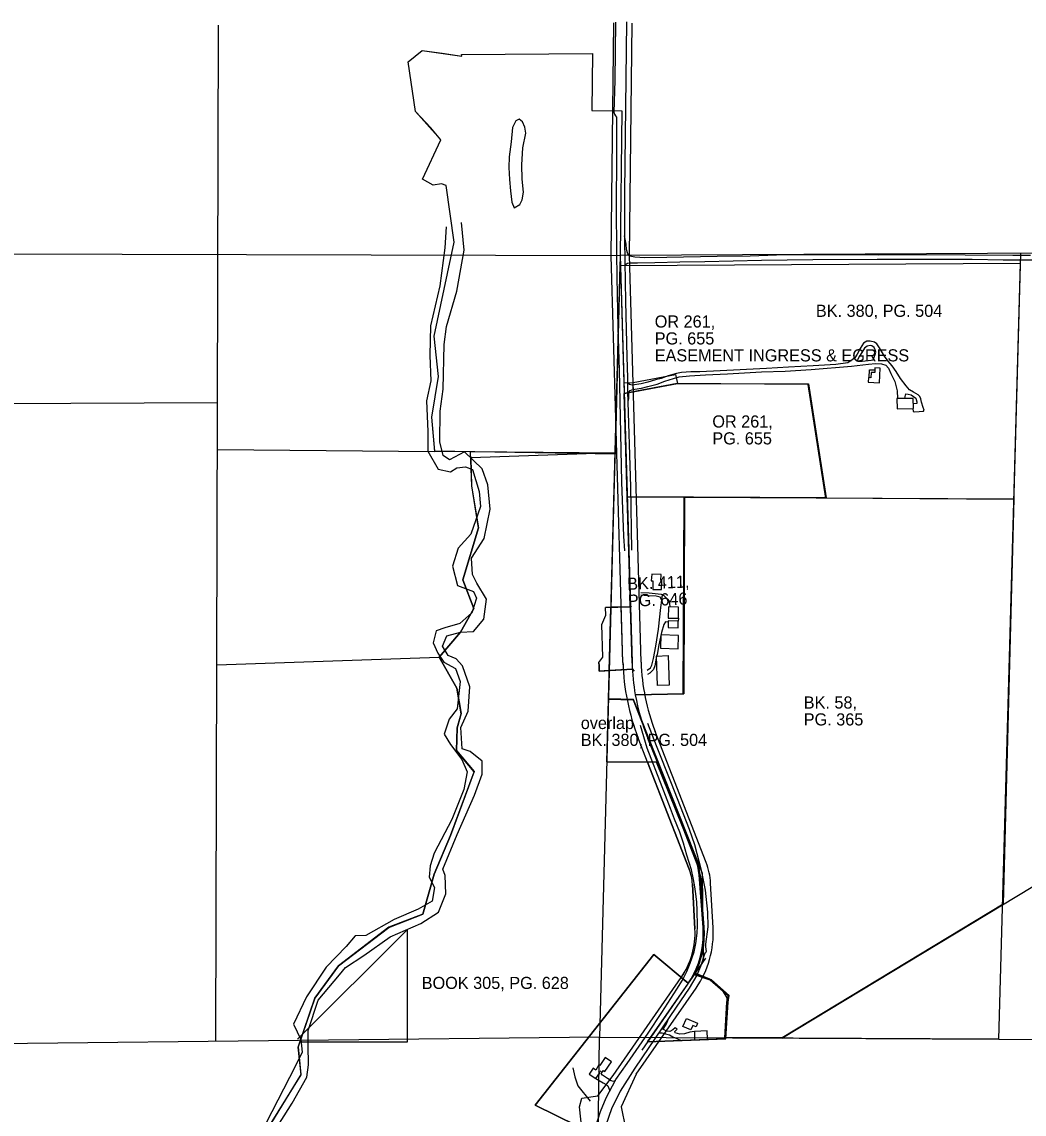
# Model space of a CAD drawing. Extents: x 171944 to 348094, y 278777 to 304794.
# Drawn here: x 175290 to 178592, y 288639 to 292239 of the extents above; entities that cross this region are included whole.
import ezdxf

# ---------------------------------------------------------------- set-up
doc = ezdxf.new("R2010")
doc.units = 0
for name, color, linetype in [('_CIVIL_CONSTRUCTION', 7, 'Continuous'), ('Default', 7, 'Continuous'), ('DR_Ditch', 7, 'Continuous'), ('DR_Pond', 7, 'Continuous'), ('DR_X_Ditch', 7, 'Continuous'), ('PF_P_Text_Strip_Grades_50', 7, 'Continuous'), ('PF_X_Text_Strip_Grade', 7, 'Continuous'), ('PV_P_Curb', 7, 'Continuous'), ('PV_X_Driveway', 7, 'Continuous'), ('RW_P_Const_Limits', 7, 'Continuous'), ('RW_P_Esmt_SH', 7, 'Continuous'), ('SV_X_Toe_of_Slope', 7, 'Continuous'), ('UT_X_Electric', 7, 'Continuous')]:
    doc.layers.add(name, color=color, linetype=linetype)

msp = doc.modelspace()

# ---------------------------------------------------------------- linework, layer by layer
at = {"layer": '_CIVIL_CONSTRUCTION'}
for p, q in [((177231.2, 291469.1), (177240.1, 292235.4)), ((177291.2, 291468.4), (177300.1, 292234.7)), ((177329.9, 290128.8), (177291.2, 291469.7)), ((177269.9, 290127.1), (177231.2, 291467.9)), ((177544.1, 289468), (177376.2, 289900)), ((177488.2, 289446.2), (177320.3, 289878.3)), ((177507, 289249), (177498.9, 289396.7)), ((177566.9, 289252.3), (177558.8, 289400)), ((177237.9, 288766.6), (177461.5, 289088.7)), ((177314, 288771), (177510.8, 289054.5)), ((177314, 288771), (177264.1, 288662.8)), ((177187.3, 288699.3), (177237.9, 288766.6)), ((177134.7, 288691.7), (177187.3, 288699.3)), ((177127, 288663.2), (177134.7, 288691.7)), ((177135, 288591.8), (177127, 288663.2)), ((177264.1, 288662.8), (177278.5, 288592.3))]:
    msp.add_line(p, q, dxfattribs=at)
for centre, radius, start, end in [((178015.8, 290148.6), 746.2, 181.6519, 201.2372), ((178015.8, 290148.6), 686.2, 181.6519, 201.2372), ((177338.1, 289387.9), 221, 3.1335, 21.2372), ((177338.1, 289387.9), 161, 3.1335, 21.2372), ((177250.9, 289235), 256.5, 325.225, 3.1335), ((177250.9, 289235), 316.5, 325.225, 3.1335)]:
    msp.add_arc(centre, radius, start, end, dxfattribs=at)
at = {"layer": 'Default'}
for p, q in [((177212.6, 290308.9), (177294.6, 290311.3)), ((177192.1, 290098.8), (177300.9, 290105.4)), ((177300.9, 290105.4), (177270.9, 290103.6)), ((177498.9, 289396.7), (177507, 289249)), ((177536.9, 289250.6), (177528.8, 289398.4)), ((177462.1, 289089.5), (177485.3, 289070.3))]:
    msp.add_line(p, q, dxfattribs=at)
for points in [[(177190.9, 290124.8), (177190.8, 290127.8), (177203.3, 290145.3), (177200.3, 290252.2), (177213.4, 290283), (177212.6, 290308.9), (177230.3, 290309.5), (177224.7, 290100.8), (177192.1, 290098.8)], [(177300.9, 290105.4), (177224.7, 290100.8), (177230.3, 290309.5), (177294.6, 290311.3), (177299.9, 290128)], [(177269.9, 290127.1), (177264.6, 290310.4), (177294.6, 290311.3), (177299.9, 290128)], [(177516.1, 289457.1), (177383.4, 289798.7), (177351.2, 289798.8), (177488.2, 289446.2)]]:
    msp.add_lwpolyline(points, dxfattribs=at)
for centre, radius, start, end in [((178015.8, 290148.6), 825.2, 181.6519, 183.4572), ((178015.8, 290148.6), 746.2, 181.6519, 183.4572), ((178015.8, 290148.6), 716.2, 181.6519, 183.4572), ((178015.8, 290148.6), 716.2, 181.6519, 183.4572), ((177338.1, 289387.9), 191, 3.135, 21.2372), ((177338.1, 289387.9), 161, 3.1335, 21.2372), ((177250.9, 289235), 256.5, 325.4566, 3.1335), ((177250.9, 289234.9), 286.5, 324.9226, 3.135)]:
    msp.add_arc(centre, radius, start, end, dxfattribs=at)
at = {"layer": 'DR_Ditch'}
for points in [[(176687.2, 291563.7), (176683.1, 291493.5), (176666.6, 291368.5), (176635.6, 291237.3), (176633.6, 291139.2), (176636.7, 291055.5), (176623.2, 290989.4), (176627.4, 290888.2), (176627.4, 290824.1), (176661.4, 290764.2), (176702, 290755.8), (176723.2, 290769.3), (176750.9, 290772), (176774.1, 290763.2), (176796.7, 290690.4), (176800.4, 290641.5), (176769.1, 290550.7), (176726.6, 290503.8), (176708.7, 290445.2), (176724.9, 290381.4), (176777.8, 290360.8), (176787.6, 290338.9), (176772.4, 290291), (176732.7, 290255.9), (176682.8, 290241.8), (176654.1, 290231.3), (176644.4, 290191.9), (176660.2, 290157.8), (176680.4, 290128.8), (176717.8, 290107.9), (176733.7, 290064.4), (176723.9, 289974.6), (176697.3, 289940.6), (176681.1, 289891.3), (176702.3, 289856.9), (176738.7, 289807.4), (176756.9, 289766.5), (176745.5, 289709.2), (176706, 289610.4), (176648.4, 289499.4), (176635.3, 289456.9), (176631.2, 289419.8), (176648.8, 289385.8), (176641.7, 289340.9), (176595.2, 289313.9), (176516, 289280.5), (176422.6, 289227.2), (176387.9, 289226.9), (176357.6, 289190.8), (176292.5, 289122.7), (176227.2, 289025.8), (176184.8, 288935.7), (176208.4, 288884.4), (176213.7, 288842.5), (176190.2, 288795.8), (176094.6, 288610.5)], [(176119.3, 288579.1), (176180.6, 288674.7), (176228.5, 288760.2), (176233.8, 288801.5), (176233.2, 288866.4), (176232.6, 288914.2), (176266.2, 289014), (176335.8, 289098.4), (176356.4, 289122), (176416.6, 289162.1), (176503.3, 289223.5), (176604.1, 289267.2), (176662.5, 289304.4), (176686.7, 289365.2), (176684.3, 289424.8), (176676.7, 289446.6), (176723.8, 289559.9), (176780.5, 289689.8), (176806.4, 289759.4), (176805.8, 289802.5), (176766.3, 289834.4), (176740.4, 289843.3), (176735.6, 289912.9), (176759.8, 289967.2), (176765.1, 290047.5), (176741, 290116), (176720.3, 290139.6), (176693.8, 290150.8), (176675.5, 290181.5), (176689.6, 290215.7), (176734.7, 290227.2), (176777.5, 290229.9), (176811.1, 290270.6), (176820, 290336.1), (176788.7, 290389.2), (176774.3, 290417.6), (176770.7, 290471.3), (176813.2, 290535.6), (176832.9, 290632.8), (176824.8, 290713), (176806.2, 290765.3), (176748.4, 290821.4), (176698.3, 290795.4), (176677.6, 290809.6), (176667, 290855), (176667.6, 290955.4), (176678.2, 291028), (176681.3, 291175.3), (176688.5, 291235), (176722.8, 291350.7), (176747.1, 291486.2), (176737.8, 291577.1)]]:
    msp.add_lwpolyline(points, dxfattribs=at)
at = {"layer": 'DR_Pond'}
msp.add_lwpolyline([(176912, 291625.9), (176929.7, 291636.5), (176938, 291651.9), (176942.1, 291677.3), (176938, 291720.9), (176936.8, 291767.6), (176940.4, 291823.1), (176950.4, 291871.5), (176946.2, 291891.5), (176939.2, 291909.8), (176928, 291918.1), (176916.8, 291912.8), (176905.6, 291890.9), (176901.4, 291843.1), (176894.9, 291793.5), (176893.8, 291759.3), (176896.1, 291719.2), (176899.7, 291682), (176904.2, 291644.3)], close=True, dxfattribs=at)
at = {"layer": 'DR_X_Ditch'}
msp.add_lwpolyline([(177104.7, 288791.8), (177111.9, 288762), (177121, 288731.6), (177161.4, 288681.4)], dxfattribs=at)
at = {"layer": 'PF_P_Text_Strip_Grades_50'}
for p, q in [((177216.7, 289799.4), (177260.3, 291435.8)), ((177261.2, 291468.8), (177260.3, 291435.8)), ((177260.3, 291435.8), (178578.2, 291443.8)), ((177261.2, 291468.8), (177300, 290124.7)), ((177261.2, 291468.8), (177284.2, 290673)), ((178578.2, 291443.8), (178507.2, 288885.9)), ((177284.2, 290673), (177472.6, 290672)), ((177300, 290124.7), (177284.2, 290673)), ((177470.3, 290024.4), (177472.6, 290672)), ((177472.6, 290672), (177470.3, 290024.4)), ((177472.6, 290672), (178557.8, 290666.3)), ((178557.8, 290666.3), (178522.7, 289330.5)), ((177200.3, 290252.2), (177213.4, 290283)), ((177212.6, 290308.9), (177230.3, 290309.5)), ((177213.4, 290283), (177212.6, 290308.9)), ((177230.3, 290309.5), (177224.7, 290100.8)), ((177230.3, 290309.5), (177224.7, 290100.8)), ((177224.7, 290100.8), (177230.3, 290309.5)), ((177230.3, 290309.5), (177224.7, 290100.8)), ((177294.6, 290311.3), (177230.3, 290309.5)), ((177294.6, 290311.3), (177230.3, 290309.5)), ((177230.3, 290309.5), (177294.6, 290311.3)), ((177294.6, 290311.3), (177298.1, 290312.9)), ((177294.6, 290311.3), (177299.9, 290128)), ((177294.6, 290311.3), (177299.9, 290128)), ((177203.3, 290145.3), (177200.3, 290252.2)), ((177190.8, 290127.8), (177203.3, 290145.3)), ((177190.9, 290124.8), (177190.8, 290127.8)), ((177300.9, 290105.4), (177224.7, 290100.8)), ((177300.9, 290105.4), (177307.1, 290099.2)), ((177224.7, 290100.8), (177192.1, 290098.8)), ((177224.7, 290100.8), (177192.1, 290098.8)), ((177310.5, 290021.1), (177470.3, 290024.4)), ((177470.3, 290024.4), (177310.5, 290021.1)), ((177510.6, 289484.1), (177351.8, 289877)), ((177380.9, 289798.6), (177216.7, 289799.4)), ((177507.5, 289483.7), (177380.9, 289798.6)), ((177534.1, 289254), (177520.7, 289427.2)), ((177537.5, 289254.5), (177523.9, 289427.6)), ((178522.7, 289330.5), (177794.3, 288890.1)), ((177542.3, 289152.4), (177332.1, 288849.7)), ((177557.5, 289080.8), (177502.4, 289099.4)), ((177561.3, 289081.3), (177506.1, 289099.8)), ((177616.1, 289029.1), (177557.5, 289080.8)), ((177619.9, 289029.6), (177561.3, 289081.3)), ((177612.6, 289007.6), (177616.1, 289029.1)), ((177616.4, 289008.2), (177619.9, 289029.6)), ((177605.4, 288890.2), (177612.6, 289007.6)), ((177609.3, 288890.8), (177616.4, 289008.2)), ((178507.2, 288885.9), (177605.4, 288890.2)), ((177794.3, 288890.1), (177609.3, 288890.8))]:
    msp.add_line(p, q, dxfattribs=at)
for points in [[(177261.2, 291468.8), (177243.9, 290813.9), (176650.1, 290823.4), (176640.5, 290936.2), (176662.2, 291070.4), (176647.6, 291203.2), (176714, 291513.2), (176687.9, 291699.4), (176672, 291704.5), (176644.3, 291700.4), (176610, 291720.8), (176670, 291850.4), (176637, 291889.5), (176586.6, 291943.9), (176562.2, 292106.6), (176608.4, 292144.3), (176682.2, 292135), (176739.7, 292125.7), (176738.5, 292131.7), (177169.4, 292134.1), (177167.1, 291947.2), (177266.7, 291945.9), (177261.2, 291468.8)], [(177261.2, 291468.8), (177274.3, 291013.8), (177449.2, 291047.2), (177880.8, 291045.3), (177939.7, 290670.1), (177284.2, 290672.9), (177274.3, 291013.8)], [(177261.2, 291468.8), (177273.3, 291049), (177303.3, 291049.9), (177443.5, 291076.7), (177449.2, 291047.2), (177304.2, 291019.5), (177303.3, 291049.9)], [(177187.8, 288566.1), (176980.6, 288668), (177371.9, 289164.9), (177485.3, 289070.9), (177534.9, 289142.3), (177531.7, 289431.9), (177304.7, 290005.3), (177222.8, 290007.5), (177244.6, 290818), (176768.7, 290801.7), (176771.2, 290709.8), (176793.6, 290571.7), (176742.1, 290400.2), (176778.7, 290305.2), (176734.4, 290227.6), (176664.5, 290145.2), (176722.9, 290042.6), (176737, 289959), (176723.4, 289912.5), (176721.6, 289837.1), (176779.3, 289767.6), (176701.3, 289557.4), (176647.6, 289430), (176610.4, 289298.4), (176498.4, 289254.7), (176332.6, 289127.8), (176254.5, 289021.1), (176199.6, 288860.3), (176209.2, 288769.2), (176108.8, 288605.8)], [(176205.7, 288876.7), (176560.2, 288876.7), (176560.2, 289247.6), (176198, 288885.5)], [(177606, 288886.8), (177351.2, 288877.1), (177508.6, 289103.8), (177554.6, 289084.7), (177597.2, 289047.3), (177611.9, 289021.6), (177606, 288886.8)]]:
    msp.add_lwpolyline(points, dxfattribs=at)
for centre, radius, start, end in [((176367.2, 290075.2), 825.2, 1.6399, 3.4452), ((178015.8, 290148.4), 825.2, 181.6399, 183.4452), ((178015.8, 290148.6), 716.2, 181.6516, 183.4572), ((178015.9, 290145.3), 716.2, 181.6519, 189.9886), ((178015.9, 290145.3), 716.2, 181.6519, 189.9886), ((178015.9, 290145.3), 716.2, 189.9887, 201.999), ((177330.2, 289412.4), 191, 4.4242, 21.8989), ((177333.5, 289412.6), 191, 4.5122, 21.9988), ((177248.4, 289231.9), 286.5, 332.4459, 4.4238), ((177252, 289232), 286.5, 332.5341, 4.512)]:
    msp.add_arc(centre, radius, start, end, dxfattribs=at)
at = {"layer": 'PF_X_Text_Strip_Grade'}
for p, q in [((175929.2, 288878.7), (175938, 292227.6)), ((178579.1, 291477.2), (178520.6, 289329.2)), ((177260.3, 291435.6), (178578.2, 291444)), ((177448.4, 291046.8), (177274.3, 291013.9)), ((174470.5, 290976.5), (175934.7, 290984.4)), ((175934.3, 290829.2), (176650.1, 290822.4)), ((177471.6, 290671.8), (177284.2, 290673)), ((175932.4, 290119.9), (176664.9, 290144.8)), ((177793.2, 288889.5), (179866.2, 290142.7)), ((177222.2, 290006.7), (177303.4, 290004.4)), ((177303.4, 290004.4), (177348.2, 289889.2)), ((177216.7, 289799.4), (177383.4, 289798.7)), ((177371.6, 289164.5), (176980.6, 288668)), ((177485.3, 289070.3), (177371.6, 289164.5)), ((177561.3, 289081.3), (177504.2, 289101.2)), ((177619.9, 289029.6), (177561.3, 289081.3)), ((177616.4, 289008.2), (177619.9, 289029.6)), ((177609.1, 288886.9), (177616.4, 289008.2)), ((177351, 288876.8), (177609.1, 288886.9)), ((176980.6, 288668), (177188.3, 288565.8))]:
    msp.add_line(p, q, dxfattribs=at)
for points in [[(177243.8, 290816.8), (176650.1, 290822.4), (176640.5, 290936.2), (176662.2, 291070.4), (176647.6, 291203.2), (176714, 291513.2), (176687.9, 291699.4), (176672, 291704.5), (176644.3, 291700.4), (176610, 291720.8), (176670, 291850.4), (176586.6, 291943.9), (176562.2, 292106.6), (176608.4, 292144.3), (176739.7, 292125.7), (176738.5, 292131.7), (177169.5, 292134.1), (177167.3, 291947.2), (177266.7, 291945.9)], [(178557, 290664.8), (177938.2, 290668.7), (177880.1, 291044.1), (177448.4, 291046.8)], [(175947, 287578.6), (176072.4, 288560.2), (176109.2, 288605.4), (176209.6, 288768.8), (176200, 288859.9), (176254.9, 289020.7), (176333, 289127.4), (176498.7, 289254.3), (176610.8, 289298), (176648, 289429.6), (176701.7, 289556.9), (176779.7, 289767.2), (176722, 289836.7), (176723.8, 289912.1), (176737.4, 289958.6), (176723.2, 290042.2), (176664.9, 290144.8), (176734.7, 290227.2), (176779.1, 290304.8), (176742.5, 290399.8), (176794, 290571.3), (176771.6, 290709.4), (176767.2, 290821.3)], [(177311, 290021.1), (177468.2, 290024.2), (177471.6, 290671.8)]]:
    msp.add_lwpolyline(points, dxfattribs=at)
at = {"layer": 'PV_P_Curb'}
for p, q in [((177303.3, 291049.9), (177443.5, 291076.7)), ((177443.5, 291076.7), (177449.2, 291047.2)), ((177273.3, 291049), (177303.3, 291049.9))]:
    msp.add_line(p, q, dxfattribs=at)
at = {"layer": 'PV_X_Driveway'}
msp.add_line((177452.6, 290273.3), (177452.2, 290263.7), dxfattribs=at)
for points in [[(178612.3, 291468.7), (178554.7, 291468.8), (178397.3, 291470.4), (178247.7, 291471), (178112.7, 291470.4), (177939.2, 291470.6), (177775.7, 291469.8), (177688.9, 291466.5), (177580.3, 291465.4), (177414.8, 291461.7), (177342.4, 291460.9), (177309.5, 291462.9), (177292.7, 291467.1), (177285.6, 291473.9), (177281.6, 291488.1), (177280, 291506), (177275.4, 291533.6)], [(177277.3, 291433.3), (177278.8, 291438.2), (177281.5, 291441.8), (177285.4, 291443.5), (177293.8, 291444.1), (177318.3, 291444.9), (177375.2, 291446.1), (177457.4, 291447.4), (177539.5, 291448.8), (177726.5, 291453.4), (177896, 291455.1), (178107.4, 291456.8), (178419.9, 291456.5), (178522.3, 291454.2), (178589.3, 291454), (178802.5, 291454.4)], [(178225.2, 290964), (178225.9, 290955), (178229.6, 290953.3), (178245.3, 290954.5), (178260.2, 290955.3), (178262.4, 290959.2), (178259, 290968.1), (178253, 290985.8), (178251.6, 290996.8), (178247.5, 291004.1), (178242.3, 291009), (178227.6, 291018.1), (178214.1, 291026.4), (178202.4, 291039.5), (178184.7, 291063), (178169.6, 291086.3), (178156.4, 291104.7), (178143.2, 291121), (178132, 291137), (178121.2, 291153.3), (178114.9, 291164.5), (178106.6, 291177.6), (178099.1, 291183.1), (178084.3, 291186.9), (178072.9, 291186.1), (178062.8, 291179.5), (178051.6, 291162.5), (178041, 291143.6), (178033.3, 291131.6), (178020.7, 291121.9), (178011.1, 291115.3), (177971.1, 291110), (177896.7, 291105.2), (177815.5, 291101.2), (177742.3, 291096.8), (177590.6, 291088.5), (177522.8, 291085.4), (177493.7, 291084.8), (177462.9, 291083.3), (177446.2, 291080), (177418.6, 291072.5), (177395.7, 291063.8), (177377.2, 291058.8), (177352.2, 291051.5), (177330, 291045.9), (177300.2, 291041.6), (177291.4, 291043.6), (177286, 291047.9)], [(177287.5, 290987.4), (177289, 290996.7), (177288.9, 291006.5), (177289.4, 291014.5), (177290.7, 291019.8), (177293.8, 291023.8), (177299.7, 291026.2), (177309.4, 291028.3), (177330.5, 291031.9), (177351.7, 291037.1), (177383, 291044.7), (177408.3, 291054.9), (177436.8, 291063.8), (177455.3, 291068.4), (177489.1, 291072.7), (177541.4, 291075.6), (177614.8, 291078.7), (177726.5, 291085.4), (177804.8, 291087.5), (177889.5, 291092.9), (178022.7, 291104.1), (178079.1, 291110.8), (178101.6, 291113.2), (178121.8, 291112), (178136.5, 291107), (178145.1, 291097.4), (178152.7, 291079.6), (178166.1, 291053.8), (178173.8, 291023), (178174.8, 290997.5)], [(178198.9, 290997.4), (178200, 291003.8), (178202.2, 291012.7), (178209.4, 291012.2), (178219.8, 291009), (178227.3, 291003.8), (178234.6, 290998.6), (178237.7, 290986.9), (178237.8, 290980.6), (178225.9, 290979.7)], [(177329.3, 290357.9), (177356.2, 290356.9), (177376.6, 290355.2), (177395.3, 290352.7), (177404.1, 290348.3), (177415.1, 290337.3), (177422, 290329.2), (177424.6, 290310.3)], [(177349.6, 290102), (177360.8, 290110.3), (177365.2, 290118.2), (177370.8, 290141), (177377.8, 290180.9), (177387.2, 290237.4), (177395.1, 290309), (177398, 290332.9), (177393, 290342.5), (177378.9, 290345.6), (177350.2, 290347.5), (177328.8, 290348.8)], [(177419.3, 290260.3), (177410.5, 290261.4), (177404.6, 290253), (177397.2, 290226.3), (177387.9, 290185.3), (177382.2, 290153.3), (177380.7, 290148.2), (177374.9, 290116.5), (177370.6, 290104.2), (177358.9, 290092.3), (177350.3, 290088)], [(177505.4, 288911.1), (177489.8, 288908.8), (177472.4, 288903.8), (177456.9, 288902.1), (177442.2, 288906.8), (177441.3, 288910.6), (177445.1, 288915.8), (177448.8, 288919.1), (177442, 288923.5), (177434.3, 288916.9), (177424.7, 288911.2), (177413.5, 288911.9), (177405.8, 288916.9), (177402.4, 288917.4), (177402.1, 288919.3), (177412.2, 288934.4), (177421.2, 288955.3)], [(177388.8, 288906.3), (177397.8, 288906.9), (177410.2, 288903), (177422.9, 288900), (177434.6, 288893.4), (177446.9, 288887.8), (177461.3, 288881.3), (177486.8, 288882.3), (177505.4, 288884.1)], [(177244.9, 288749.6), (177239.1, 288746.2), (177231, 288748.8), (177219.3, 288756), (177202.7, 288766.8), (177198.7, 288772.4), (177201.3, 288776.8)], [(177181.1, 288756), (177191.3, 288749.5), (177205.3, 288741.8), (177214.3, 288736.3), (177220.2, 288731.9), (177226.4, 288716)]]:
    msp.add_lwpolyline(points, dxfattribs=at)
msp.add_lwpolyline([(178042.1, 291125), (178039.2, 291121.7), (178043.4, 291120), (178058.4, 291120.7), (178087.7, 291123.8), (178093.7, 291125), (178101, 291142.5), (178102.9, 291150.2), (178100.4, 291157.9), (178097, 291165.8), (178089.4, 291171.2), (178084.3, 291172), (178074.6, 291170.1), (178066.1, 291162.9), (178056.7, 291149.1), (178049.2, 291136.5)], close=True, dxfattribs=at)
at = {"layer": 'RW_P_Const_Limits'}
for p, q in [((174190.2, 291476.8), (177261.2, 291468.8)), ((179901.1, 291483.2), (177261.2, 291468.8)), ((177261.2, 291468.8), (177192.5, 288892.2)), ((177193.1, 288892.2), (174584.2, 288864.3)), ((177157.1, 286252.3), (177192.7, 288892.2)), ((177193.1, 288892.2), (178507.8, 288886.2)), ((178507.8, 288886.2), (182479.3, 288853.3))]:
    msp.add_line(p, q, dxfattribs=at)
at = {"layer": 'RW_P_Esmt_SH'}
for p, q in [((177200.3, 290252.2), (177213.4, 290283)), ((177264.6, 290310.4), (177212.6, 290308.9)), ((177213.4, 290283), (177212.6, 290308.9)), ((177203.3, 290145.3), (177200.3, 290252.2)), ((177190.8, 290127.8), (177203.3, 290145.3)), ((177190.9, 290124.8), (177190.8, 290127.8)), ((177270.9, 290103.6), (177192.1, 290098.8)), ((177270.9, 290103.6), (177192.1, 290098.8))]:
    msp.add_line(p, q, dxfattribs=at)
msp.add_arc((178015.8, 290148.6), 825.2, 181.6519, 183.4572, dxfattribs=at)
at = {"layer": 'SV_X_Toe_of_Slope'}
for points in [[(178077.6, 291051.2), (178114.8, 291049.4), (178116.9, 291097), (178099.8, 291098), (178100, 291083.3), (178087.4, 291083.5), (178086.1, 291065.8), (178078.6, 291066.2)], [(178173, 290963), (178226.6, 290964), (178225.6, 290997.8), (178172.7, 290997.4)], [(177368.1, 290368.1), (177396.7, 290367.7), (177397.5, 290397.2), (177394.4, 290397.2), (177395.4, 290417.2), (177364.6, 290418.6), (177363.2, 290396.4), (177368.8, 290396.6)], [(177419.1, 290273.9), (177452.6, 290273.3), (177453.1, 290309.2), (177420.2, 290310.5)], [(177418.9, 290242.3), (177451.4, 290241.3), (177452.2, 290263.7), (177419.4, 290265.2)], [(177393.8, 290174.1), (177451.4, 290172.1), (177452.4, 290216.5), (177395.2, 290218.6)], [(177380.7, 290148.2), (177418.8, 290149.9), (177422.2, 290052.5), (177383.7, 290051.8)], [(177493.7, 288916.7), (177467.5, 288927.9), (177478.9, 288954.1), (177515.5, 288938.1), (177510.6, 288926), (177500.2, 288930.4)], [(177505.4, 288884.1), (177548, 288885.7), (177547, 288912.9), (177505.4, 288911.1)], [(177158.7, 288770.5), (177181.1, 288756), (177194, 288775.1), (177190.9, 288777.4), (177193.6, 288781.1), (177201.3, 288776.8), (177205.7, 288782.6), (177209.9, 288779.3), (177231.9, 288811.3), (177210.9, 288825), (177193.6, 288799.4), (177190.9, 288801.1), (177180.2, 288784.1), (177177.6, 288786), (177171.3, 288790.1)]]:
    msp.add_lwpolyline(points, close=True, dxfattribs=at)
msp.add_lwpolyline([(178081.5, 291066.2), (178082.5, 291092.4), (178099.7, 291091.7)], dxfattribs=at)
at = {"layer": 'UT_X_Electric'}
for points in [[(177245.3, 292237.9), (177243, 292045.8), (177240, 291941.6), (177241.6, 291935), (177245.3, 291929), (177248.2, 291924.6), (177248.2, 291795.8), (177247.3, 291631.4), (177248.2, 291477.4), (177249.6, 291396.4), (177253.2, 291231.2), (177257.2, 291091), (177259.6, 290988.3), (177265.2, 290721.6), (177271.6, 290543.9), (177275.5, 290495.7)], [(177299.5, 290497.2), (177296.2, 290706.3), (177286.1, 291020.4), (177285.7, 291065.2), (177284, 291135.2), (177278.9, 291317.1), (177276.8, 291449.5), (177275.7, 291521.7), (177275.6, 291678.6), (177281, 292051.9), (177283.1, 292238.9)], [(177351.2, 289927.4), (177379.1, 289853.3), (177428.4, 289729.4), (177488.4, 289577.6), (177505.2, 289527.7), (177528, 289443), (177540.8, 289376.5), (177548.7, 289304.8), (177549.2, 289256.3), (177542.3, 289199.4), (177542.1, 289190.3), (177543.6, 289175.1), (177541.5, 289169.9), (177539.4, 289168.9), (177525.4, 289125.2), (177513.6, 289096.7), (177488, 289054), (177445.3, 288991), (177399.3, 288922.8), (177309, 288790.6), (177261.2, 288714), (177232.6, 288656.2), (177213.1, 288602.2)], [(177179.9, 288595.3), (177195.7, 288647.5), (177214.7, 288693), (177246.5, 288752.5), (177283.9, 288805.9), (177353, 288905.4), (177398, 288973.6), (177447.5, 289050.2), (177466.3, 289080.4), (177480.3, 289108.6), (177491.3, 289136.1), (177504.4, 289173.6), (177510.2, 289201.6), (177514.6, 289235.7), (177515.6, 289259.9), (177514.5, 289310.3), (177513.5, 289337.1), (177509.5, 289365.1), (177506.4, 289387.8), (177502.4, 289411.8), (177495.6, 289443.8), (177480.7, 289492.6), (177469.3, 289531.6), (177457.7, 289567.6), (177440.2, 289611.2), (177427, 289646.2), (177399.2, 289717.7), (177349.6, 289845.4), (177327.4, 289920.2)]]:
    msp.add_lwpolyline(points, dxfattribs=at)

# ---------------------------------------------------------------- texts
at = {"layer": 'PF_P_Text_Strip_Grades_50'}
for s, p in [('BK. 380, PG. 504', (177905.5, 291266.6)), ('OR 261,', (177374.6, 291231.2)), ('PG. 655', (177374.6, 291175.5)), ('EASEMENT INGRESS & EGRESS', (177374.6, 291119.7)), ('OR 261,', (177564.4, 290901.8)), ('PG. 655', (177564.4, 290846.1)), ('BK. 58,', (177865.5, 289975.5)), ('PG. 365', (177865.5, 289919.8)), ('overlap ', (177131, 289908)), ('BK. 380, PG. 504', (177131, 289852.3)), ('BOOK 305, PG. 628', (176607, 289051.3))]:
    msp.add_text(s, height=40, dxfattribs=at).set_placement(p)
for s, p in [('BK. 411,', (177284.6, 290366.5)), ('PG. 646', (177286.8, 290310.8))]:
    msp.add_text(s, height=40, rotation=2.2186, dxfattribs=at).set_placement(p)

doc.saveas('drawing.dxf')
